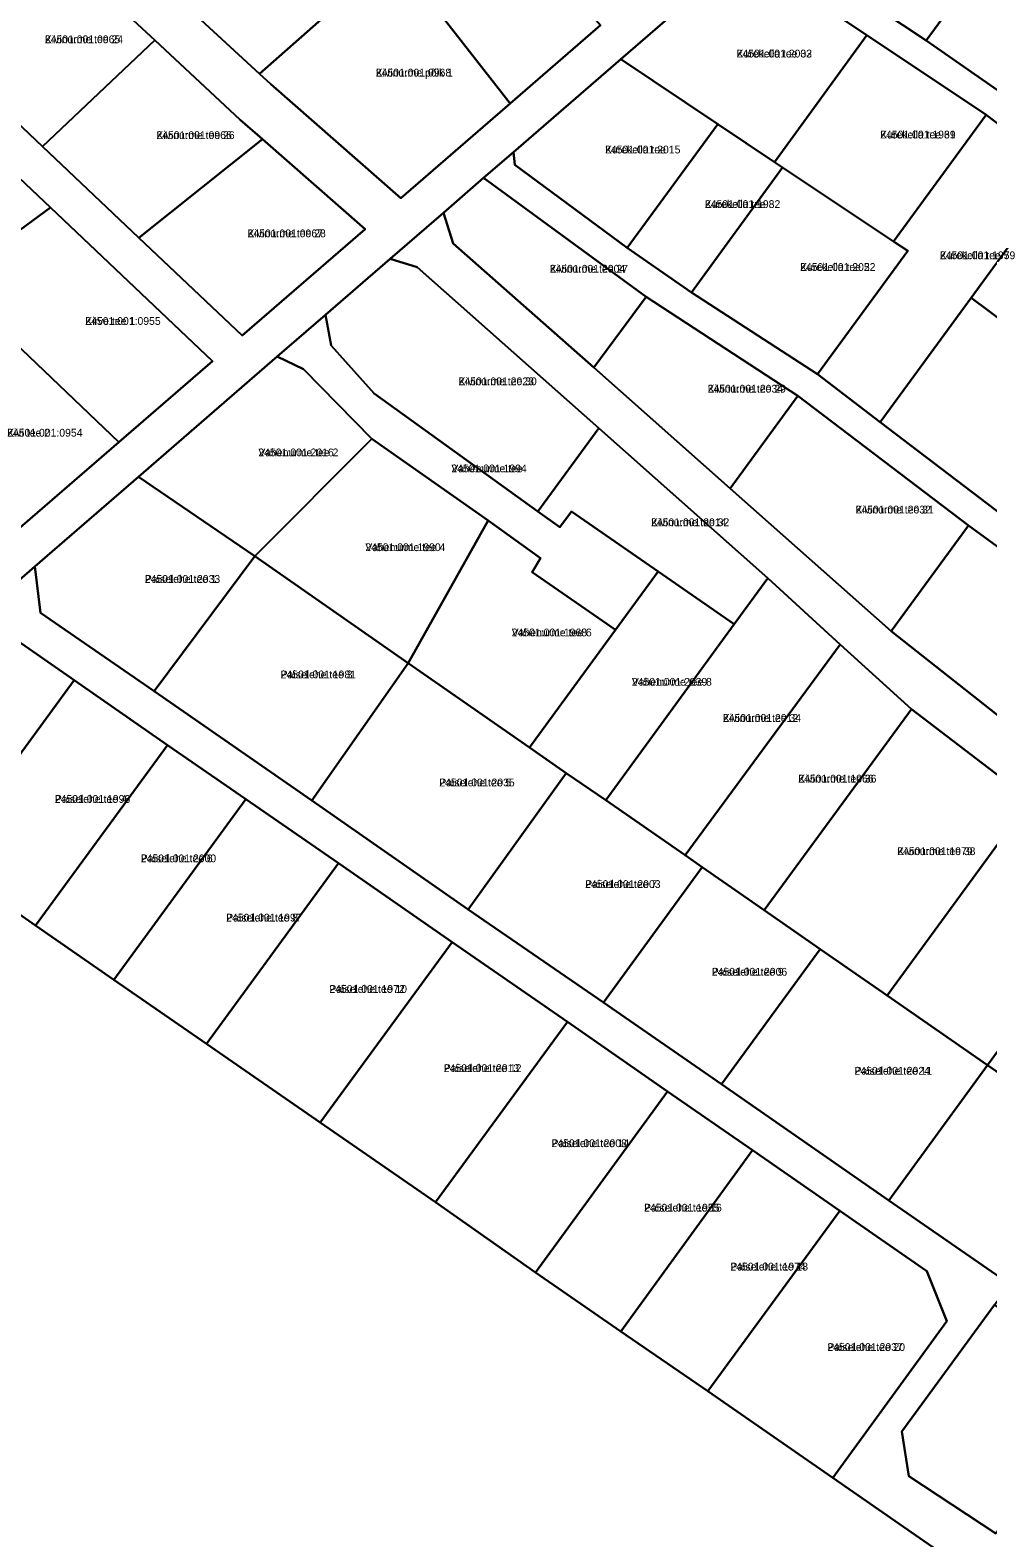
# Model space of a CAD drawing. Extents: x 551291 to 575799, y 6581704 to 6610137.
# Drawn here: x 559526.5 to 559710.7, y 6593302.2 to 6593592.3 of the extents above; entities that cross this region are included whole.
import ezdxf

# ---------------------------------------------------------------- set-up
doc = ezdxf.new("R2010")
doc.units = 0
for name, color, linetype in [('L_AADRESS', 7, 'Continuous'), ('PIIR', 7, 'Continuous'), ('TUNNUS', 7, 'Continuous')]:
    doc.layers.add(name, color=color, linetype=linetype)

msp = doc.modelspace()

# ---------------------------------------------------------------- linework, layer by layer
at = {"layer": 'PIIR'}
for points in [[(559570.63, 6593583.9), (559552.09, 6593601.08), (559588, 6593633.11), (559604.37, 6593613.76), (559596.54, 6593606.83)], [(559672.09, 6593614.42), (559693.82, 6593633.25), (559705.07, 6593624.88), (559719.13, 6593618), (559698.86, 6593590.33), (559672.54, 6593607.88)], [(559618.85, 6593578.22), (559596.54, 6593606.83), (559604.37, 6593613.76), (559612.37, 6593620.83), (559636.22, 6593593.26)], [(559698.86, 6593590.33), (559719.13, 6593618), (559742.94, 6593604.41), (559721.24, 6593574.74)], [(559528.87, 6593569.93), (559508.31, 6593589.38), (559529.63, 6593609.71), (559550.44, 6593590.38)], [(559572.76, 6593581.92), (559570.63, 6593583.9), (559596.54, 6593606.83), (559618.85, 6593578.22), (559597.8, 6593560)], [(559640.1, 6593586.76), (559663.71, 6593607.18), (559687.46, 6593591.34), (559669.66, 6593566.96), (559658.81, 6593574.21)], [(559547.42, 6593552.38), (559528.87, 6593569.93), (559550.44, 6593590.38), (559566.91, 6593575.08), (559571.16, 6593571.36)], [(559669.66, 6593566.96), (559687.46, 6593591.34), (559710.41, 6593576.02), (559692.59, 6593551.66), (559671.24, 6593565.88)], [(559619.47, 6593568.85), (559640.1, 6593586.76), (559658.81, 6593574.21), (559641.36, 6593550.45), (559619.71, 6593566.41)], [(559500.51, 6593554.18), (559486.14, 6593567.07), (559504.89, 6593582.3), (559530.39, 6593558.18), (559511.11, 6593544.05)], [(559692.59, 6593551.66), (559710.41, 6593576.02), (559725.11, 6593564.86), (559707.51, 6593540.85), (559690.02, 6593516.88), (559677.94, 6593526.12), (559695.35, 6593549.85)], [(559641.36, 6593550.45), (559658.81, 6593574.21), (559669.66, 6593566.96), (559671.24, 6593565.88), (559653.71, 6593541.88)], [(559567.28, 6593533.59), (559547.42, 6593552.38), (559571.16, 6593571.36), (559590.92, 6593554.06)], [(559653.71, 6593541.88), (559671.24, 6593565.88), (559692.59, 6593551.66), (559695.35, 6593549.85), (559677.94, 6593526.12)], [(559605.98, 6593557.17), (559613.73, 6593563.91), (559645.01, 6593541.04), (559634.96, 6593527.43), (559607.89, 6593551.26)], [(559707.51, 6593540.85), (559725.11, 6593564.86), (559745.13, 6593549.68), (559727.67, 6593525.82)], [(559521.99, 6593533.67), (559511.11, 6593544.05), (559530.39, 6593558.18), (559561.59, 6593528.66), (559543.57, 6593513.06)], [(559583.32, 6593537.54), (559595.76, 6593548.33), (559600.95, 6593546.73), (559635.89, 6593515.75), (559624.16, 6593499.69), (559592.66, 6593522.41), (559584.37, 6593531.68)], [(559634.96, 6593527.43), (559645.01, 6593541.04), (559674.17, 6593522), (559661.15, 6593504.14)], [(559690.02, 6593516.88), (559707.51, 6593540.85), (559727.67, 6593525.82), (559731.33, 6593523.02), (559713.65, 6593498.94)], [(559574.02, 6593529.52), (559583.32, 6593537.54), (559584.37, 6593531.68), (559592.66, 6593522.41), (559624.16, 6593499.69), (559628.38, 6593496.71), (559630.66, 6593499.73), (559647.32, 6593488.19), (559639.08, 6593476.97), (559623.06, 6593488.07), (559624.65, 6593490.74), (559614.57, 6593497.98), (559592.23, 6593513.68), (559579.1, 6593527.1)], [(559522.2, 6593494.56), (559500.8, 6593514.9), (559521.99, 6593533.67), (559543.57, 6593513.06)], [(559547.35, 6593506.39), (559574.02, 6593529.52), (559579.1, 6593527.1), (559592.23, 6593513.68), (559569.71, 6593491.14)], [(559661.15, 6593504.14), (559674.17, 6593522), (559707.01, 6593497.03), (559692.15, 6593476.66)], [(559569.71, 6593491.14), (559592.23, 6593513.68), (559614.57, 6593497.98), (559599.18, 6593470.5)], [(559624.16, 6593499.69), (559635.89, 6593515.75), (559668.38, 6593486.88), (559661.95, 6593478.03), (559647.32, 6593488.19), (559630.66, 6593499.73), (559628.38, 6593496.71)], [(559527.37, 6593489.15), (559547.35, 6593506.39), (559569.71, 6593491.14), (559550.34, 6593465.13), (559528.49, 6593480.24)], [(559599.18, 6593470.5), (559614.57, 6593497.98), (559624.65, 6593490.74), (559623.06, 6593488.07), (559639.08, 6593476.97), (559622.55, 6593454.31)], [(559692.15, 6593476.66), (559707.01, 6593497.03), (559733.05, 6593478.06), (559717.41, 6593456.71)], [(559550.34, 6593465.13), (559569.71, 6593491.14), (559599.18, 6593470.5), (559580.68, 6593444.08)], [(559639.08, 6593476.97), (559647.32, 6593488.19), (559661.95, 6593478.03), (559637.21, 6593444.19), (559629.64, 6593449.38), (559622.55, 6593454.31)], [(559661.95, 6593478.03), (559668.38, 6593486.88), (559682.3, 6593474.12), (559652.49, 6593433.56), (559637.21, 6593444.19)], [(559516.09, 6593479.32), (559516.73, 6593479.92), (559534.96, 6593467.27), (559509.57, 6593432.53), (559488.67, 6593447.02)], [(559652.49, 6593433.56), (559682.3, 6593474.12), (559696.03, 6593461.71), (559667.73, 6593423.01), (559655.76, 6593431.28)], [(559580.68, 6593444.08), (559599.18, 6593470.5), (559622.55, 6593454.31), (559629.64, 6593449.38), (559610.78, 6593423.14)], [(559509.57, 6593432.53), (559534.96, 6593467.27), (559552.9, 6593454.78), (559527.53, 6593420.06)], [(559667.73, 6593423.01), (559696.03, 6593461.71), (559718.87, 6593444.25), (559691.39, 6593406.61), (559678.5, 6593415.53)], [(559527.53, 6593420.06), (559552.9, 6593454.78), (559568, 6593444.34), (559542.6, 6593409.62)], [(559610.78, 6593423.14), (559629.64, 6593449.38), (559637.21, 6593444.19), (559652.49, 6593433.56), (559655.76, 6593431.28), (559636.76, 6593405.25)], [(559542.6, 6593409.62), (559568, 6593444.34), (559585.8, 6593432.04), (559560.41, 6593397.31)], [(559691.39, 6593406.61), (559718.87, 6593444.25), (559738.39, 6593431.07), (559710.7, 6593393.19)], [(559560.41, 6593397.31), (559585.8, 6593432.04), (559607.68, 6593416.88), (559582.29, 6593382.14)], [(559636.76, 6593405.25), (559655.76, 6593431.28), (559667.73, 6593423.01), (559678.5, 6593415.53), (559659.5, 6593389.52)], [(559710.7, 6593393.19), (559738.39, 6593431.07), (559759.83, 6593417.58), (559731.42, 6593378.82)], [(559582.29, 6593382.14), (559607.68, 6593416.88), (559629.86, 6593401.51), (559604.45, 6593366.81)], [(559659.5, 6593389.52), (559678.5, 6593415.53), (559691.39, 6593406.61), (559710.7, 6593393.19), (559691.7, 6593367.16)], [(559604.45, 6593366.81), (559629.86, 6593401.51), (559649.13, 6593388.13), (559623.74, 6593353.31)], [(559691.7, 6593367.16), (559710.7, 6593393.19), (559731.42, 6593378.82), (559746.91, 6593368.1), (559724.92, 6593338.06), (559712.01, 6593347.07), (559714.97, 6593351.07)], [(559623.74, 6593353.31), (559649.13, 6593388.13), (559665.46, 6593376.84), (559640.12, 6593341.93)], [(559640.12, 6593341.93), (559665.46, 6593376.84), (559682.28, 6593365.16), (559656.88, 6593330.46)], [(559656.88, 6593330.46), (559682.28, 6593365.16), (559699.02, 6593353.52), (559702.83, 6593343.92), (559680.91, 6593313.81)], [(559694.16, 6593322.68), (559712.01, 6593347.07), (559724.92, 6593338.06), (559733.53, 6593332.13), (559712.26, 6593303.04), (559695.55, 6593314.08)]]:
    msp.add_lwpolyline(points, close=True, dxfattribs=at)
for points in [[(559508.31, 6593589.38), (559528.87, 6593569.93), (559547.42, 6593552.38), (559567.28, 6593533.59), (559590.92, 6593554.06), (559571.16, 6593571.36), (559566.91, 6593575.08), (559550.44, 6593590.38), (559529.63, 6593609.71), (559507.82, 6593629.95)], [(559663.71, 6593607.18), (559640.1, 6593586.76), (559619.47, 6593568.85), (559613.73, 6593563.91), (559605.98, 6593557.17), (559595.76, 6593548.33), (559583.32, 6593537.54), (559574.02, 6593529.52), (559547.35, 6593506.39), (559527.37, 6593489.15), (559516.73, 6593479.92)], [(559725.11, 6593564.86), (559710.41, 6593576.02), (559687.46, 6593591.34), (559663.71, 6593607.18)], [(559672.54, 6593607.88), (559698.86, 6593590.33), (559721.24, 6593574.74)], [(559552.09, 6593601.08), (559570.63, 6593583.9), (559572.76, 6593581.92), (559597.8, 6593560), (559618.85, 6593578.22), (559636.22, 6593593.26)], [(559522.2, 6593494.56), (559543.57, 6593513.06), (559561.59, 6593528.66), (559530.39, 6593558.18), (559504.89, 6593582.3)], [(559733.05, 6593478.06), (559707.01, 6593497.03), (559674.17, 6593522), (559645.01, 6593541.04), (559613.73, 6593563.91), (559619.47, 6593568.85), (559619.71, 6593566.41), (559641.36, 6593550.45), (559653.71, 6593541.88), (559677.94, 6593526.12), (559690.02, 6593516.88), (559713.65, 6593498.94)], [(559718.87, 6593444.25), (559696.03, 6593461.71), (559682.3, 6593474.12), (559668.38, 6593486.88), (559635.89, 6593515.75), (559600.95, 6593546.73), (559595.76, 6593548.33), (559605.98, 6593557.17), (559607.89, 6593551.26), (559634.96, 6593527.43), (559661.15, 6593504.14), (559692.15, 6593476.66), (559717.41, 6593456.71)], [(559745.59, 6593268.96), (559680.91, 6593313.81), (559702.83, 6593343.92), (559699.02, 6593353.52), (559682.28, 6593365.16), (559665.46, 6593376.84), (559649.13, 6593388.13), (559629.86, 6593401.51), (559607.68, 6593416.88), (559585.8, 6593432.04), (559568, 6593444.34), (559552.9, 6593454.78), (559534.96, 6593467.27), (559516.73, 6593479.92), (559527.37, 6593489.15), (559528.49, 6593480.24), (559550.34, 6593465.13), (559580.68, 6593444.08), (559610.78, 6593423.14), (559636.76, 6593405.25), (559659.5, 6593389.52), (559691.7, 6593367.16), (559714.97, 6593351.07)], [(559406.07, 6593272.34), (559429.98, 6593308.7), (559445.78, 6593336.09), (559455.53, 6593367.82), (559471.85, 6593408.56), (559482.38, 6593437.64), (559488.67, 6593447.02), (559509.57, 6593432.53), (559527.53, 6593420.06), (559542.6, 6593409.62), (559560.41, 6593397.31), (559582.29, 6593382.14), (559604.45, 6593366.81), (559623.74, 6593353.31), (559640.12, 6593341.93), (559656.88, 6593330.46), (559680.91, 6593313.81), (559745.59, 6593268.96)], [(559712.01, 6593347.07), (559694.16, 6593322.68), (559695.55, 6593314.08), (559712.26, 6593303.04)]]:
    msp.add_lwpolyline(points, dxfattribs=at)

# ---------------------------------------------------------------- texts
at = {"layer": 'L_AADRESS'}
for s, p in [('Kivinurme tee 24', (559529.31, 6593589.82)), ('Kurekella tee 33', (559662.4, 6593587.07)), ('Kivinurme põik 1', (559592.98, 6593583.41)), ('Kivinurme tee 26', (559550.77, 6593571.38)), ('Kurekella tee 31', (559690.03, 6593571.49)), ('Kurekella tee 1', (559637.09, 6593568.61)), ('Kurekella tee 3', (559656.3, 6593558.11)), ('Kivinurme tee 28', (559568.31, 6593552.48)), ('Kurekella tee 7', (559701.52, 6593548.26)), ('Kivinurme tee 27', (559626.46, 6593545.67)), ('Kurekella tee 5', (559674.62, 6593546)), ('Kirve tee 1', (559537.09, 6593535.62)), ('Kivinurme tee 30', (559608.9, 6593524.01)), ('Kivinurme tee 29', (559656.83, 6593522.59)), ('Kivi tee 2', (559522.05, 6593514.12)), ('Vahenurme tee 2', (559570.39, 6593510.33)), ('Vahenurme tee', (559607.52, 6593507.25)), ('Kivinurme tee 31', (559685.28, 6593499.33)), ('Kivinurme tee 32', (559645.94, 6593496.89)), ('Vahenurme tee 4', (559590.97, 6593492.09)), ('Paiselehe tee 1', (559548.54, 6593485.98)), ('Vahenurme tee 6', (559619.13, 6593475.69)), ('Paiselehe tee 3', (559574.67, 6593467.61)), ('Vahenurme tee 8', (559642.25, 6593466.19)), ('Kivinurme tee 34', (559659.75, 6593459.24)), ('Paiselehe tee 5', (559605.2, 6593446.82)), ('Kivinurme tee 36', (559674.26, 6593447.56)), ('Paiselehe tee 4', (559531.23, 6593443.65)), ('Paiselehe tee 6', (559547.77, 6593432.22)), ('Kivinurme tee 38', (559693.3, 6593433.6)), ('Paiselehe tee 7', (559633.27, 6593427.27)), ('Paiselehe tee 8', (559564.2, 6593420.82)), ('Paiselehe tee 9', (559657.63, 6593410.4)), ('Paiselehe tee 10', (559584.04, 6593407.09)), ('Paiselehe tee 12', (559606.07, 6593391.86)), ('Paiselehe tee 11', (559685.09, 6593391.35)), ('Paiselehe tee 14', (559626.79, 6593377.41)), ('Paiselehe tee 16', (559644.6, 6593365.01)), ('Paiselehe tee 18', (559661.2, 6593353.67)), ('Paiselehe tee 20', (559679.86, 6593338.19))]:
    msp.add_text(s, height=1.5, dxfattribs=at).set_placement(p)
at = {"layer": 'TUNNUS'}
for s, p in [('24501:001:0965', (559529.31, 6593589.82)), ('24501:001:2002', (559662.4, 6593587.07)), ('24501:001:0968', (559592.98, 6593583.41)), ('24501:001:0966', (559550.77, 6593571.38)), ('24501:001:1969', (559690.03, 6593571.49)), ('24501:001:2015', (559637.09, 6593568.61)), ('24501:001:1982', (559656.3, 6593558.11)), ('24501:001:0967', (559568.31, 6593552.48)), ('24501:001:1959', (559701.52, 6593548.26)), ('24501:001:2004', (559626.46, 6593545.67)), ('24501:001:2022', (559674.62, 6593546)), ('24501:001:0955', (559537.09, 6593535.62)), ('24501:001:2023', (559608.9, 6593524.01)), ('24501:001:2034', (559656.83, 6593522.59)), ('24501:001:0954', (559522.05, 6593514.12)), ('24501:001:2016', (559570.39, 6593510.33)), ('24501:001:1994', (559607.52, 6593507.25)), ('24501:001:2032', (559685.28, 6593499.33)), ('24501:001:2014', (559645.94, 6593496.89)), ('24501:001:1990', (559590.97, 6593492.09)), ('24501:001:2033', (559548.54, 6593485.98)), ('24501:001:1968', (559619.13, 6593475.69)), ('24501:001:1981', (559574.67, 6593467.61)), ('24501:001:2039', (559642.25, 6593466.19)), ('24501:001:2012', (559659.75, 6593459.24)), ('24501:001:2035', (559605.2, 6593446.82)), ('24501:001:1966', (559674.26, 6593447.56)), ('24501:001:1996', (559531.23, 6593443.65)), ('24501:001:2000', (559547.77, 6593432.22)), ('24501:001:1979', (559693.3, 6593433.6)), ('24501:001:2003', (559633.27, 6593427.27)), ('24501:001:1997', (559564.2, 6593420.82)), ('24501:001:2006', (559657.63, 6593410.4)), ('24501:001:1972', (559584.04, 6593407.09)), ('24501:001:2013', (559606.07, 6593391.86)), ('24501:001:2024', (559685.09, 6593391.35)), ('24501:001:2008', (559626.79, 6593377.41)), ('24501:001:1955', (559644.6, 6593365.01)), ('24501:001:1974', (559661.2, 6593353.67)), ('24501:001:2037', (559679.86, 6593338.19))]:
    msp.add_text(s, height=1.5, dxfattribs=at).set_placement(p)

doc.saveas('drawing.dxf')
